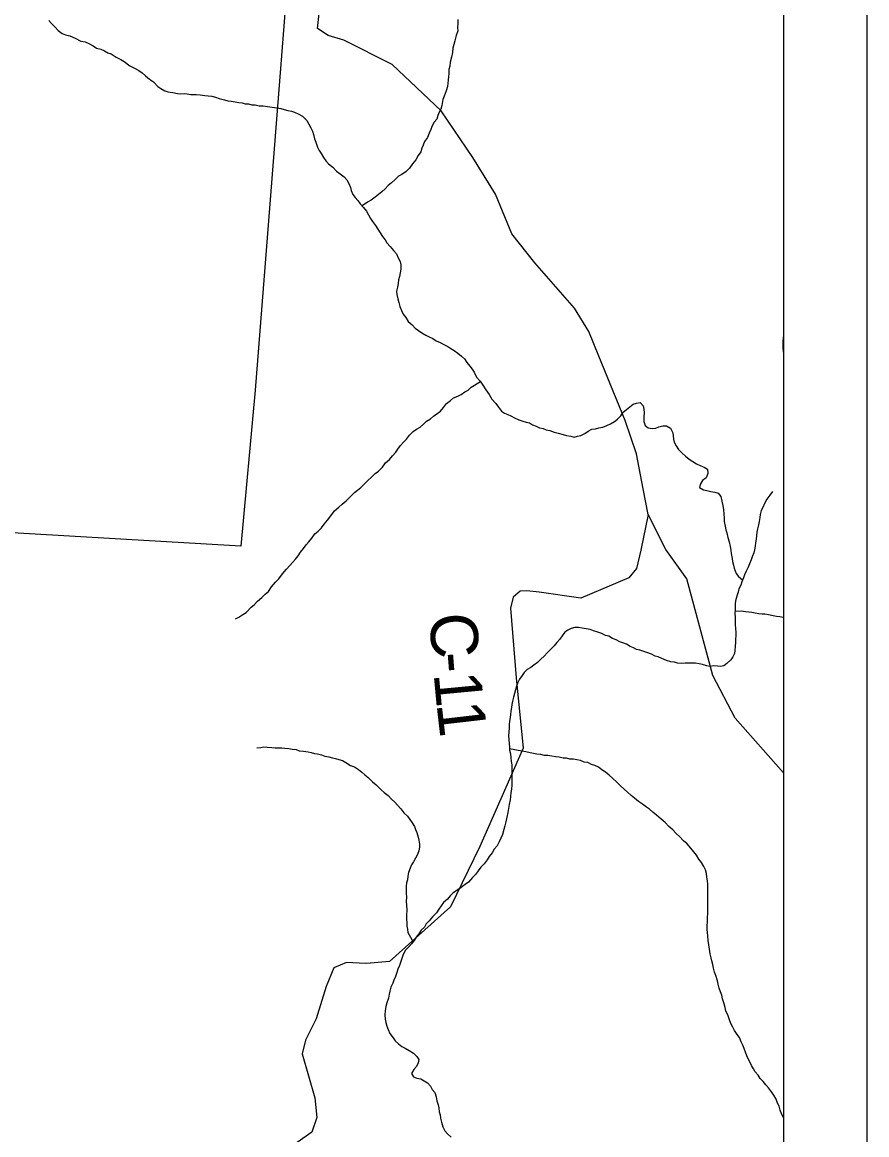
# Model space of a CAD drawing. Extents: x -15 to 405, y -40 to 87.
# Drawn here: x 7.989 to 9.004, y 16.927 to 18.265 of the extents above; entities that cross this region are included whole.
import ezdxf

# ---------------------------------------------------------------- set-up
doc = ezdxf.new("R2010")
doc.units = 0
for name, color, linetype in [('GM_X_Adjacent_County_Text', 7, 'Continuous'), ('GM_X_Airport_Location_Class_2', 7, 'Continuous'), ('GM_X_Minor_Lake', 7, 'Continuous'), ('GM_X_Township', 7, 'Continuous'), ('GM_X_Township_Text', 7, 'Continuous')]:
    doc.layers.add(name, color=color, linetype=linetype)

msp = doc.modelspace()

# ---------------------------------------------------------------- linework, layer by layer
at = {"layer": 'GM_X_Adjacent_County_Text'}
for points in [[(8.0212, 18.2671), (8.0243, 18.2633), (8.0285, 18.2588), (8.0323, 18.255), (8.0372, 18.2512), (8.041, 18.2497), (8.0464, 18.2486), (8.0528, 18.2459), (8.0597, 18.2422), (8.0646, 18.2414), (8.0692, 18.2392), (8.0745, 18.2365), (8.0783, 18.2339), (8.0836, 18.2324), (8.0882, 18.2305), (8.092, 18.2282), (8.0962, 18.2267), (8.1019, 18.2229), (8.1076, 18.2199), (8.1118, 18.2176), (8.1186, 18.2123), (8.1239, 18.2097), (8.1293, 18.2067), (8.1331, 18.204), (8.1372, 18.2006), (8.1422, 18.1965), (8.1468, 18.1931), (8.1521, 18.1878), (8.1559, 18.1851), (8.1605, 18.1825)], [(8.513, 18.2683), (8.513, 18.2634), (8.5126, 18.2585), (8.5127, 18.2547), (8.5108, 18.249), (8.5093, 18.2425), (8.5081, 18.238), (8.507, 18.2338), (8.5063, 18.2285), (8.5051, 18.2228), (8.5036, 18.2167), (8.5033, 18.2122), (8.5021, 18.208), (8.5022, 18.2034), (8.5018, 18.1993), (8.5014, 18.1955), (8.5007, 18.1917), (8.5003, 18.1875), (8.4988, 18.1822), (8.4965, 18.1761), (8.495, 18.1719), (8.4935, 18.1647), (8.4924, 18.1605), (8.4905, 18.1567), (8.4886, 18.1526), (8.4875, 18.1484), (8.4845, 18.1446), (8.4814, 18.1396), (8.4803, 18.1358), (8.4784, 18.1313), (8.4765, 18.1263), (8.4728, 18.1214), (8.4713, 18.1172), (8.4697, 18.1134), (8.4682, 18.1092), (8.4652, 18.1047), (8.4622, 18.0994), (8.4584, 18.0944), (8.4546, 18.0895), (8.4508, 18.0853), (8.4455, 18.0819)], [(8.1605, 18.1825), (8.1643, 18.1813), (8.1703, 18.1802), (8.1757, 18.1791), (8.1798, 18.1787), (8.1836, 18.1791), (8.1874, 18.1787), (8.192, 18.178), (8.1981, 18.178), (8.203, 18.1776), (8.2087, 18.1769), (8.2125, 18.1765), (8.2171, 18.1758), (8.2216, 18.1747), (8.2258, 18.1731), (8.2323, 18.1716), (8.2361, 18.1705), (8.2402, 18.1701), (8.2452, 18.169), (8.2494, 18.1683), (8.2535, 18.1679), (8.2573, 18.1668), (8.2611, 18.1668), (8.2653, 18.1657), (8.2691, 18.1657), (8.274, 18.1645), (8.2786, 18.1642), (8.2839, 18.1634), (8.2896, 18.1627), (8.2953, 18.1619), (8.2999, 18.1612), (8.3041, 18.1601), (8.3086, 18.1589), (8.3128, 18.1578), (8.3166, 18.1567), (8.3215, 18.1544), (8.3261, 18.1518), (8.3311, 18.1468), (8.3337, 18.1423), (8.336, 18.1378), (8.3379, 18.134), (8.3395, 18.1298), (8.3406, 18.1245), (8.3421, 18.1207), (8.3441, 18.1146), (8.3463, 18.1108), (8.3486, 18.1071), (8.3513, 18.1021), (8.354, 18.0983), (8.3574, 18.0946), (8.3627, 18.0904), (8.3669, 18.0859), (8.3715, 18.0824), (8.376, 18.079), (8.3795, 18.0753), (8.3818, 18.0711), (8.3837, 18.0662), (8.3844, 18.0624), (8.3864, 18.0578), (8.3894, 18.054), (8.3925, 18.0503), (8.3955, 18.0465), (8.3993, 18.0419), (8.4031, 18.0378), (8.4054, 18.0332), (8.4077, 18.029), (8.4104, 18.0253), (8.4138, 18.0203), (8.4165, 18.0162), (8.4195, 18.0116), (8.4222, 18.0071), (8.4256, 18.0033), (8.4275, 17.9995), (8.4313, 17.9953), (8.4355, 17.9904), (8.439, 17.9862), (8.4412, 17.9817), (8.4435, 17.9772), (8.4443, 17.973), (8.4443, 17.968), (8.4436, 17.9635), (8.4428, 17.9589), (8.4417, 17.9551), (8.441, 17.9506), (8.4402, 17.9464), (8.4391, 17.9415), (8.4395, 17.9373), (8.4406, 17.9324), (8.4418, 17.9278), (8.4433, 17.9229), (8.4452, 17.9183), (8.4471, 17.9138), (8.4502, 17.9096), (8.4532, 17.9051), (8.4578, 17.9009), (8.4616, 17.8971), (8.4654, 17.8941), (8.4696, 17.8915), (8.4742, 17.8884), (8.4783, 17.8866), (8.4829, 17.8843)], [(8.4455, 18.0819), (8.4417, 18.0796), (8.4376, 18.0758), (8.433, 18.0716), (8.4292, 18.0686), (8.4255, 18.0644), (8.4213, 18.0609), (8.4175, 18.0575), (8.4133, 18.0545), (8.4088, 18.051), (8.4042, 18.0484), (8.3977, 18.0439)], [(8.4829, 17.8843), (8.4867, 17.8816), (8.4917, 17.8798), (8.497, 17.8767), (8.5008, 17.8748), (8.5046, 17.8726), (8.5084, 17.8699), (8.513, 17.8669), (8.5171, 17.8631), (8.5209, 17.8601), (8.5236, 17.8556), (8.5274, 17.8514), (8.5301, 17.8476), (8.5324, 17.8438), (8.5354, 17.8378), (8.5396, 17.8332), (8.5427, 17.8283), (8.5465, 17.8226), (8.5507, 17.8173), (8.5537, 17.8116), (8.5587, 17.8063), (8.5617, 17.8018), (8.5652, 17.7972), (8.569, 17.7946), (8.5728, 17.7931), (8.5766, 17.7916), (8.5808, 17.7889), (8.5861, 17.7867), (8.591, 17.7852), (8.5952, 17.784), (8.599, 17.7829), (8.6028, 17.7806), (8.607, 17.7791), (8.6112, 17.7769), (8.6153, 17.7761), (8.6191, 17.7746), (8.6233, 17.7739), (8.6286, 17.772), (8.6336, 17.7708), (8.6393, 17.769), (8.6435, 17.7678), (8.6488, 17.7671), (8.6526, 17.766), (8.6568, 17.7671), (8.6609, 17.7679), (8.6655, 17.7702), (8.6697, 17.7732), (8.6738, 17.7755), (8.6784, 17.7759), (8.6822, 17.777), (8.6871, 17.7778), (8.692, 17.7797), (8.6966, 17.782), (8.7011, 17.7847), (8.7049, 17.7873), (8.7087, 17.7915), (8.7114, 17.7953), (8.7155, 17.7991), (8.7197, 17.8022), (8.7235, 17.8056), (8.7277, 17.8067), (8.7322, 17.8075), (8.7356, 17.8033), (8.7364, 17.7996), (8.7368, 17.795), (8.7364, 17.7908), (8.7365, 17.7848), (8.738, 17.7798), (8.7418, 17.7772), (8.7464, 17.7764), (8.7509, 17.7768), (8.7547, 17.7784), (8.7593, 17.7795), (8.7638, 17.7795), (8.7684, 17.7765), (8.7714, 17.7712), (8.7718, 17.7674), (8.7722, 17.7636), (8.773, 17.7598), (8.7753, 17.7553), (8.7783, 17.7511), (8.7821, 17.7469), (8.7867, 17.7431), (8.7909, 17.7394), (8.7955, 17.7367), (8.8, 17.7337), (8.805, 17.7314), (8.8091, 17.7299), (8.8129, 17.7273), (8.8133, 17.7223), (8.8115, 17.717), (8.8069, 17.7136), (8.8043, 17.709), (8.8035, 17.7052), (8.8081, 17.7026), (8.8123, 17.7015), (8.8172, 17.7003), (8.8218, 17.6996), (8.8259, 17.6985), (8.829, 17.6943), (8.8301, 17.689)], [(8.9045, 17.8884), (8.904, 17.8853), (8.9037, 17.8808), (8.9037, 17.877), (8.9037, 17.8732), (8.9041, 17.869), (8.9045, 17.8678)], [(8.2457, 17.5471), (8.2495, 17.5491), (8.2545, 17.5525), (8.2582, 17.5551), (8.2643, 17.5612), (8.2681, 17.5643), (8.2719, 17.5685), (8.2772, 17.573), (8.2813, 17.5768), (8.2851, 17.5803), (8.2889, 17.5856), (8.2938, 17.5913), (8.2976, 17.5955), (8.3022, 17.6015), (8.3067, 17.6069), (8.3109, 17.6114), (8.3139, 17.6152), (8.3177, 17.619), (8.3207, 17.6232), (8.3237, 17.6274), (8.3271, 17.632), (8.3305, 17.6361), (8.3336, 17.6399), (8.3374, 17.6445), (8.3408, 17.6495), (8.3449, 17.6529), (8.3491, 17.6567), (8.3521, 17.6612), (8.3563, 17.6658), (8.3601, 17.6711), (8.3646, 17.6772), (8.3699, 17.6818), (8.3737, 17.6852), (8.3786, 17.6894), (8.3836, 17.6943), (8.3885, 17.6993), (8.3923, 17.7019), (8.3964, 17.7054), (8.4006, 17.7096), (8.4048, 17.7137), (8.4089, 17.7175), (8.4135, 17.7221), (8.4176, 17.7251), (8.4222, 17.7297), (8.426, 17.735), (8.4305, 17.7388), (8.4343, 17.7434), (8.4381, 17.7476), (8.4407, 17.7514), (8.4441, 17.7556), (8.4475, 17.7598), (8.451, 17.7636), (8.4547, 17.7681), (8.4593, 17.7727), (8.4631, 17.7753), (8.4676, 17.778), (8.4714, 17.7814), (8.4752, 17.7852), (8.4798, 17.7879), (8.4835, 17.791), (8.4877, 17.794), (8.4919, 17.797), (8.4957, 17.8016), (8.4994, 17.8062), (8.504, 17.81), (8.5078, 17.813), (8.5127, 17.8153), (8.5169, 17.8172), (8.5214, 17.8203), (8.5252, 17.8225), (8.529, 17.826), (8.54, 17.8327)], [(8.8912, 17.7005), (8.8878, 17.696), (8.8844, 17.6914), (8.8814, 17.6861), (8.8795, 17.6812), (8.8776, 17.6774), (8.8765, 17.6728), (8.8758, 17.669), (8.875, 17.6644), (8.8743, 17.6603), (8.8731, 17.6557), (8.8724, 17.6515), (8.872, 17.6477), (8.8717, 17.6432), (8.8709, 17.6386), (8.8702, 17.6348), (8.8694, 17.6303), (8.8687, 17.6265), (8.8668, 17.6219), (8.8656, 17.6181), (8.8634, 17.6136), (8.8619, 17.6094), (8.8596, 17.6045), (8.8577, 17.6003), (8.8562, 17.5965), (8.8543, 17.5919), (8.8532, 17.5877), (8.8509, 17.5832), (8.8498, 17.5794), (8.8487, 17.5756), (8.8472, 17.5707), (8.8464, 17.5661), (8.8461, 17.5623), (8.8461, 17.5581), (8.8457, 17.5536), (8.8461, 17.5494), (8.8461, 17.5449), (8.8461, 17.5407), (8.8465, 17.5354), (8.8469, 17.5312), (8.8469, 17.527), (8.8465, 17.5228), (8.8466, 17.5191), (8.8462, 17.5141), (8.8458, 17.5092), (8.8454, 17.5054), (8.8436, 17.5016), (8.8409, 17.4978), (8.8364, 17.4936), (8.8326, 17.4909), (8.8288, 17.4898), (8.825, 17.4902), (8.8204, 17.4909), (8.8159, 17.4901), (8.8121, 17.4909), (8.8071, 17.4924), (8.803, 17.4931), (8.7988, 17.4939), (8.7942, 17.4939), (8.79, 17.4939), (8.7862, 17.4939), (8.7813, 17.4935), (8.7771, 17.4938), (8.7733, 17.495), (8.7691, 17.4957), (8.7638, 17.4972), (8.7581, 17.4995), (8.7539, 17.5014), (8.7501, 17.5025), (8.7456, 17.5048), (8.7399, 17.5066), (8.7353, 17.5082), (8.7315, 17.5097), (8.7277, 17.5104), (8.7239, 17.5123), (8.7201, 17.5142), (8.7155, 17.5168), (8.7114, 17.5183), (8.7076, 17.5198), (8.7034, 17.5221), (8.6988, 17.5236), (8.6943, 17.5263), (8.6905, 17.5274), (8.6859, 17.5297), (8.681, 17.5312), (8.676, 17.533), (8.6718, 17.5346), (8.6673, 17.5353), (8.6623, 17.536), (8.6578, 17.5368), (8.6536, 17.5368), (8.649, 17.5356), (8.6453, 17.5337), (8.6415, 17.5314), (8.6381, 17.5269), (8.6354, 17.5227), (8.632, 17.5189), (8.6286, 17.5147), (8.6244, 17.5102), (8.6203, 17.5063), (8.6165, 17.5022)], [(8.8301, 17.689), (8.8313, 17.6837), (8.8321, 17.6784), (8.8325, 17.6734), (8.8329, 17.6681), (8.8332, 17.6643), (8.8344, 17.6587), (8.8352, 17.6545), (8.8363, 17.6507), (8.8375, 17.645), (8.839, 17.6401), (8.8402, 17.6344), (8.8409, 17.6298), (8.8413, 17.626), (8.8425, 17.62), (8.8432, 17.6162), (8.8444, 17.612), (8.8452, 17.6082), (8.8474, 17.6019), (8.8504, 17.5983), (8.8552, 17.5941)], [(8.9045, 17.5487), (8.9042, 17.5488), (8.9, 17.5495), (8.8958, 17.5499), (8.892, 17.5507), (8.8863, 17.5522), (8.8821, 17.5528), (8.8787, 17.5529), (8.8749, 17.5533), (8.8704, 17.554), (8.8662, 17.5548), (8.8628, 17.5553), (8.8586, 17.5559), (8.854, 17.5566), (8.8459, 17.5562)], [(8.6165, 17.5022), (8.6127, 17.4987), (8.6085, 17.4946), (8.6044, 17.4915), (8.6006, 17.4888), (8.5964, 17.4862), (8.5926, 17.4828), (8.59, 17.479), (8.5869, 17.4748), (8.585, 17.4706), (8.5835, 17.4664), (8.582, 17.4619), (8.5809, 17.4573), (8.5798, 17.4531), (8.5787, 17.4482), (8.5779, 17.4444), (8.5772, 17.4406), (8.5764, 17.4364), (8.576, 17.4322), (8.5757, 17.4285), (8.5749, 17.4243), (8.5746, 17.4201), (8.5746, 17.4155), (8.5742, 17.4118), (8.5738, 17.4064), (8.5742, 17.4023), (8.5746, 17.397), (8.575, 17.3932), (8.575, 17.3894), (8.5762, 17.3848), (8.5766, 17.3803), (8.577, 17.3757), (8.5777, 17.3715), (8.5777, 17.367), (8.5777, 17.3621), (8.5778, 17.3575), (8.5778, 17.3526), (8.5778, 17.3473), (8.5774, 17.3423), (8.5767, 17.3385), (8.5763, 17.3336), (8.5756, 17.3294), (8.5744, 17.3241), (8.5737, 17.3192), (8.5729, 17.3142), (8.5718, 17.3089), (8.5707, 17.3032), (8.5692, 17.2983), (8.5681, 17.2937), (8.5666, 17.288), (8.5647, 17.2835), (8.5624, 17.2789), (8.5601, 17.2744), (8.5567, 17.2702), (8.5541, 17.266), (8.5507, 17.2614), (8.548, 17.2573), (8.5446, 17.2527), (8.5405, 17.2485), (8.5374, 17.244), (8.5344, 17.2402), (8.5306, 17.236), (8.5257, 17.2306), (8.5215, 17.2276), (8.517, 17.2242), (8.5117, 17.2204), (8.5071, 17.2177), (8.5037, 17.2139), (8.5003, 17.2101), (8.4958, 17.2059), (8.4927, 17.2021), (8.4901, 17.1979), (8.4871, 17.1937), (8.4825, 17.1888), (8.4784, 17.1842), (8.4746, 17.1804), (8.4727, 17.1766), (8.4689, 17.1728), (8.4659, 17.1683), (8.4628, 17.1645), (8.4602, 17.1603), (8.4572, 17.1565), (8.4538, 17.1527), (8.45, 17.1489), (8.4473, 17.1436), (8.4458, 17.1398), (8.4443, 17.1352), (8.4428, 17.1303), (8.4409, 17.1257), (8.4394, 17.1219), (8.4379, 17.117), (8.436, 17.1128), (8.4345, 17.109), (8.4323, 17.1041), (8.4311, 17.0995), (8.4304, 17.0957), (8.4293, 17.0912), (8.4274, 17.0855), (8.4262, 17.0809), (8.4255, 17.0756), (8.4251, 17.071)], [(8.2712, 17.392), (8.2758, 17.3924), (8.2796, 17.3932), (8.2834, 17.3928), (8.2891, 17.3924), (8.2932, 17.3921), (8.297, 17.3921), (8.3012, 17.3921), (8.305, 17.3917), (8.3096, 17.3914), (8.3138, 17.3906), (8.3183, 17.3902), (8.3221, 17.3887), (8.3271, 17.388), (8.3328, 17.3872), (8.3365, 17.3865), (8.3404, 17.3854), (8.3441, 17.385), (8.3491, 17.3835), (8.3529, 17.382), (8.3578, 17.3812), (8.362, 17.3801), (8.3658, 17.3794), (8.3696, 17.3779), (8.3742, 17.3767), (8.378, 17.3745), (8.3837, 17.3707), (8.3886, 17.3692), (8.3936, 17.3662), (8.3974, 17.3627), (8.4012, 17.3597), (8.405, 17.3563), (8.4103, 17.3514), (8.4145, 17.3476), (8.4206, 17.3416), (8.4244, 17.3382), (8.429, 17.3347), (8.4332, 17.3302), (8.437, 17.3268), (8.4404, 17.323), (8.4442, 17.3188), (8.448, 17.3139), (8.4522, 17.3101), (8.4552, 17.306), (8.4579, 17.3018), (8.4606, 17.2976), (8.4621, 17.2938), (8.4636, 17.2901), (8.4652, 17.2848), (8.4659, 17.281), (8.4667, 17.2764), (8.4667, 17.2726), (8.466, 17.2684), (8.4645, 17.2639), (8.4618, 17.2593), (8.4596, 17.2551), (8.4573, 17.2513), (8.4554, 17.2475), (8.4535, 17.2422), (8.4528, 17.2377), (8.4524, 17.2335), (8.4513, 17.2297), (8.4509, 17.2259), (8.4509, 17.2213), (8.4509, 17.2176), (8.4513, 17.2119), (8.4506, 17.2077), (8.451, 17.2024), (8.4514, 17.1974), (8.451, 17.191), (8.451, 17.1861), (8.4514, 17.1815), (8.4514, 17.1777), (8.4522, 17.1739), (8.4526, 17.1701), (8.4591, 17.1588)], [(8.7472, 17.3147), (8.7434, 17.3185), (8.7396, 17.3207), (8.7347, 17.3245), (8.7301, 17.3275), (8.7252, 17.3317), (8.7214, 17.3347), (8.7168, 17.3389), (8.713, 17.3423), (8.708, 17.3468), (8.7042, 17.351), (8.6989, 17.3555), (8.6947, 17.3593), (8.6905, 17.3627), (8.686, 17.3657), (8.6818, 17.3688), (8.6776, 17.3707), (8.6734, 17.3722), (8.6692, 17.3744), (8.6647, 17.3748), (8.6605, 17.3767), (8.6559, 17.3778), (8.6518, 17.3786), (8.6476, 17.3785), (8.6434, 17.3797), (8.6396, 17.3797), (8.6347, 17.3808), (8.6301, 17.3812), (8.6259, 17.3819), (8.621, 17.3827), (8.6172, 17.383), (8.6126, 17.3842), (8.6077, 17.3845), (8.6039, 17.3853), (8.5997, 17.386), (8.5948, 17.3875), (8.5898, 17.3883), (8.575, 17.3909)], [(8.9045, 16.9474), (8.902, 16.9519), (8.9005, 16.9561), (8.899, 16.961), (8.8971, 16.9648), (8.8955, 16.9694), (8.8929, 16.9743), (8.8898, 16.9785), (8.8864, 16.983), (8.8833, 16.9868), (8.8799, 16.9906), (8.8765, 16.9944), (8.8738, 16.9982), (8.8704, 17.0023), (8.8685, 17.0061), (8.8658, 17.0099), (8.8635, 17.0152), (8.8612, 17.0198), (8.8593, 17.0247), (8.857, 17.0304), (8.8555, 17.0345), (8.8536, 17.0383), (8.8516, 17.0436), (8.8486, 17.0474), (8.8456, 17.052), (8.8436, 17.0561), (8.841, 17.0607), (8.8394, 17.0649), (8.8375, 17.0709), (8.8352, 17.0755), (8.8341, 17.0796), (8.8329, 17.0842), (8.831, 17.0903), (8.8302, 17.0948), (8.8287, 17.0986), (8.8272, 17.1031), (8.826, 17.1077), (8.8249, 17.1119), (8.823, 17.1183), (8.8214, 17.1221), (8.8203, 17.127), (8.8195, 17.1316), (8.8184, 17.1358), (8.8176, 17.1396), (8.8164, 17.1445), (8.8153, 17.1498), (8.8145, 17.1551), (8.8137, 17.1604), (8.8133, 17.1661), (8.813, 17.1699), (8.8126, 17.1737), (8.8125, 17.1782), (8.8129, 17.1828), (8.8129, 17.1877), (8.8133, 17.1934), (8.8133, 17.1972), (8.8136, 17.2018), (8.8136, 17.2059), (8.8136, 17.2101), (8.8136, 17.2147), (8.8136, 17.2188), (8.8136, 17.223), (8.8136, 17.2283), (8.8132, 17.2321), (8.8124, 17.2367), (8.812, 17.2408), (8.8105, 17.2454), (8.8086, 17.2492), (8.8059, 17.2541), (8.8028, 17.2583), (8.7998, 17.2632), (8.7967, 17.267), (8.7929, 17.2715), (8.7887, 17.2765), (8.7842, 17.2802), (8.7792, 17.2855), (8.7754, 17.2889), (8.7712, 17.2935), (8.7667, 17.2976), (8.7621, 17.3022), (8.7575, 17.3064), (8.7518, 17.3113), (8.7472, 17.3147)], [(8.4251, 17.071), (8.4255, 17.0657), (8.4263, 17.0619), (8.4274, 17.0574), (8.429, 17.0532), (8.4309, 17.0487), (8.4351, 17.0434), (8.4374, 17.0396), (8.4416, 17.0362), (8.4457, 17.0328), (8.4495, 17.0309), (8.4545, 17.0282), (8.4594, 17.0248), (8.4636, 17.021), (8.4659, 17.0173), (8.4652, 17.0131), (8.4633, 17.0089), (8.4599, 17.0051), (8.4572, 17.0005), (8.4595, 16.9964), (8.4637, 16.9949), (8.4683, 16.9941), (8.4724, 16.9915), (8.4762, 16.9892), (8.48, 16.985), (8.482, 16.9812), (8.485, 16.9775), (8.4869, 16.9722), (8.4877, 16.9676), (8.4892, 16.9627), (8.49, 16.9589), (8.4904, 16.9543), (8.4915, 16.9505), (8.4919, 16.9467), (8.4931, 16.9418), (8.495, 16.9361), (8.4973, 16.9316), (8.5003, 16.9278), (8.5049, 16.924)]]:
    msp.add_lwpolyline(points, dxfattribs=at)
at = {"layer": 'GM_X_Airport_Location_Class_2'}
msp.add_lwpolyline([(7.3224, 18.7155), (8.3348, 18.6585), (8.3012, 18.2299), (8.2693, 17.8222), (8.2519, 17.6347), (7.6952, 17.6671), (7.2533, 17.6973), (7.2656, 17.8881), (7.2968, 18.3475)], close=True, dxfattribs=at)
at = {"layer": 'GM_X_Township'}
for p, q in [((9.0045, 20.9941), (9.0045, 13.9941)), ((8.9045, 20.8941), (8.9045, 14.0941)), ((8.9045, 20.8941), (8.9045, 14.0941))]:
    msp.add_line(p, q, dxfattribs=at)
at = {"layer": 'GM_X_Township_Text'}
for points in [[(8.7415, 17.6728), (8.7357, 17.7036), (8.7275, 17.7457), (8.7141, 17.7858), (8.6822, 17.8631), (8.6703, 17.893), (8.6531, 17.921), (8.6054, 17.9754), (8.5779, 18.0102), (8.5583, 18.0583), (8.5308, 18.1022), (8.4929, 18.1582), (8.4338, 18.2141), (8.3756, 18.2434), (8.3569, 18.249), (8.344, 18.2573), (8.3498, 18.3082), (8.3831, 18.3444), (8.4045, 18.378)], [(8.7415, 17.6728), (8.733, 17.6299), (8.7277, 17.6079), (8.7183, 17.5968), (8.6607, 17.5723), (8.6105, 17.5792), (8.5957, 17.5811), (8.5877, 17.5806), (8.5794, 17.5734), (8.576, 17.5601), (8.5828, 17.4762), (8.5915, 17.3917), (8.5393, 17.2734), (8.5039, 17.2007), (8.4305, 17.1351), (8.4079, 17.1332), (8.4076, 17.1331)], [(8.9045, 17.3621), (8.8462, 17.4278), (8.8194, 17.4793), (8.7882, 17.5956), (8.763, 17.6308), (8.7415, 17.6728)], [(8.4076, 17.1331), (8.402, 17.1327), (8.3788, 17.1341), (8.3637, 17.1275), (8.3546, 17.1051), (8.3427, 17.0663), (8.3295, 17.0405), (8.3257, 17.0241), (8.3408, 16.9711), (8.3435, 16.9475), (8.3372, 16.9297), (8.2709, 16.883)]]:
    msp.add_lwpolyline(points, dxfattribs=at)

# ---------------------------------------------------------------- texts
at = {"layer": 'GM_X_Minor_Lake'}
for s, rotation, p in [('C', 274.0703, (8.4784, 17.5527)), ('-', 274.5449, (8.4818, 17.5057)), ('1', 275.3985, (8.4837, 17.4815)), ('1', 276.6101, (8.4871, 17.4453))]:
    msp.add_text(s, height=0.0568, rotation=rotation, dxfattribs=at).set_placement(p)

doc.saveas('drawing.dxf')
